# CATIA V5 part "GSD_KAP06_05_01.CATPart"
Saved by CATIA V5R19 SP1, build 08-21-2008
Part number: GSD_CYLINDER_01
Definition: Beispielmodell für Funktion Zylinder / Cylinder.
Description: CATIA V5 Flächenmodellierung  Copyrigth (c) 2009 Maik Hertha IT Consultants
Bounding box of the stored display mesh (mm): x 50 to 50, y 50 to 50, z 0 to 105
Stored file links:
  C:\Users\Maik\CAD Daten\modelle\gsd_buch_uebung\GSD_KAP06_05_01.CATPart
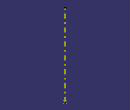
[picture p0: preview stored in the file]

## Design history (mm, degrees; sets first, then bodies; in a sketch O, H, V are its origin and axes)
AxisSystem1 "Absolute Axis System": origin (0, 0, 0), X (1, 0, 0), Y (0, 1, 0), Z (0, 0, 1)
Set1
  Plane1: type Offset, Offset 0, RefPlane XY plane of AxisSystem1
  Point1: type OnPlane, Support Plane1, Direction (1, 0, 0), H 50, V 50
  Line1: type PtDir, Direction Plane1, Start 0, End 105, RefPoint Point1
Body1 (main body)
